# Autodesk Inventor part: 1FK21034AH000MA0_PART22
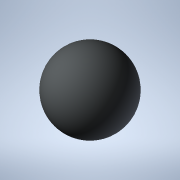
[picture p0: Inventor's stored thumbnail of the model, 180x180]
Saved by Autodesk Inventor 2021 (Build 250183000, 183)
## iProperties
Created: 2025-04
Part Number: 1FK21034AH000MA0_PART22
Material: Generic
Catalog Web Link: www.3dfindit.com
Description: -Servo synchronous motor
Document SubType Name: Modeling
Designer: psAdmin
Mass: 0.113097 g
Surface Area: 1.13097 cm^2
Volume: 0.113097 cm^3
Density: 1 g/cm^3
Appearance: PSOLRGB-212-217-219
Category: PARTsolutions
Title: 1FK21034AH000MA0_PART22
Author: Cadenas PARTsolutions
Comments: Servo synchronous motor
Sending System: PARTsolutions
Preprocessor: ST-DEVELOPER v19.3
PSOL_IDENT_0: {$CADENAS_DATA/23d-libs/siemens_ag/_cat_/ec/b7/1fk21034ah000ma0.prj},216 {VTYP=3D},{NB=1FK21034AH000
PSOL_IDENT_1: MA0_PART22},{LINA=1FK21034AH000MA0_PART22},{NN=1FK21034AH000MA0_PART22},{NOPRJ=TRUE},{DATE=19.08.202
PSOL_IDENT_2: 5 14:01:05},{GEOMDATE=30.07.2025 02:01:02},{VERSION=},{LINEID=10},{WBVAR=},{WBNUMERIC=}  {NB=1FK2103
PSOL_IDENT_3: 4AH000MA0_PART22},{LINA=1FK21034AH000MA0_PART22},{KT=DUMMY},{PREVIEW=../../../_pool_/7c/50/p_d211_xx
PSOL_IDENT_4: _00932j.png},{DESCSHORT=SIMOTICS S-1FK2 HD, SINAMICS S210 3AC 400V-480V, 1.01 Nm, 4500 rpm},{DESCLON
PSOL_IDENT_5: G=SIMOTICS S-1FK2 HD servo motor M0=1.27 Nm; PN = 0.48 kW at nN=4500 rpm (380-480 V); PN = 0.3 kW at
PSOL_IDENT_6: nN=2500 rpm (200-240 V); degree of protection IP64; cylindrical shaft D14 x 30 mm; absolute encoder
PSOL_IDENT_7: 22-bit + 12-bit multiturn (encoder AM22DQC); with OCC interface; plug size M17, rotatable; SIMOTICS
PSOL_IDENT_8: S-1FK2 servomotorfor a wide range of uses in industrial environments. SIMOTICS S‑1FK2 servomotors a
PSOL_IDENT_9: re compact synchronous motors with a high dynamic performance that set themselves apart as a result
PSOL_IDENT_10: of their high power density, degree of protection and overload capability. The motors are available
PSOL_IDENT_11: in two variants: as High Dynamic variant (highest dynamic performance as a result of the low intrins
PSOL_IDENT_12: ic moment of inertia for applications demanding a high dynamic performance with low moved masses) -
PSOL_IDENT_13: and as Compact variant (precise and stable closed-loop control for medium up to large moved masses a
PSOL_IDENT_14: s a result of a medium intrinsic moment of inertia). SIMOTICSS‑1FK2 servomotors fully exploit their
PSOL_IDENT_15: strengths in a system with the SINAMICSS210 frequency converter and simple connection using the one
PSOL_IDENT_16: cable connection (OCC). Advantages include the short control and positioning times, fast and precise
PSOL_IDENT_17: correction of disturbing quantities as well as stable control with a high dynamic performance. The
PSOL_IDENT_18: servo motors can be configured to address a wide range of requirements. For example with and without
PSOL_IDENT_19: holding brake, IP64 or IP65 degree of protection, singleturn or multiturn absolute encoders - to na
PSOL_IDENT_20: me just a few. Further, the servomotors are available in different shaft heights extending from 20 t
PSOL_IDENT_21: o 100. A shaft sealing ring is available to achieve an IP65 degree of protection and for subsequent
PSOL_IDENT_22: mounting at the motor or as spare part. SIMOTICS - the optimum motor for each and every motion contr
PSOL_IDENT_23: ol application.},{INTNO=4034106444822},{SUPPLIERALTNO=1FK2103-4AH00-0MA0},{MANUID=1FK21034AH000MA0},
PSOL_IDENT_24: {MANUNAME=Siemens},{MANUTYPEDESC=SYNCHRONOUS MOTOR 1FK2 HD 1,27 NM},{AAU732=SIMOTICS},{AAO057=S-1FK2
PSOL_IDENT_25: },{AAU734=SIMOTICS S-1FK2 HD servo motor M0=1.27 Nm; PN = 0.48 kW at nN=4500 rpm (380-480 V); PN = 0
PSOL_IDENT_26: .3 kW at nN=2500 rpm (200-240 V); degree of protection IP64; cylindrical shaft D14 x 30 mm; absolute
PSOL_IDENT_27: encoder 22-bit + 12-bit multiturn (encoder AM22DQC); with OCC interface; plug size M17, rotatable;}
PSOL_IDENT_28: ,{AAW338=SYNCHRONOUS MOTOR 1FK2 HD 1,27 NM},{AAO742=SIMOTICS},{AAO663=4034106444822},{NOCUPEROU=1},{
PSOL_IDENT_29: PRICEQUANTITY=1},{QUANTITYMIN=1},{QUANTITYINT=1},{CTN=85015100},{COO=RO},{AAO676=1FK2103-4AH00-0MA0}
PSOL_IDENT_30: ,{AAO677=Siemens AG},{ORDERUNIT=C62},{CONTENTUNIT=C62}
NB: 1FK21034AH000MA0_PART22
NT: Servo synchronous motor
NBSYN: $MANUID._PART22
LINA: 1FK21034AH000MA0_PART22
CATALOG: SIEMENS
PREVIEW: ../../../_pool_/7c/50/p_d211_xx_00932j.png
DESCSHORT: SIMOTICS S-1FK2 HD, SINAMICS S210 3AC 400V-480V, 1.01 Nm, 4500 rpm
DESCLONG: SIMOTICS S-1FK2 HD servo motor M0=1.27 Nm; PN = 0.48 kW at nN=4500 rpm (380-480 V); PN = 0.3 kW at nN=2500 rpm (200-240 V); degree of protection IP64; cylindric
INTNO: 4034106444822
SUPPLIERALTNO: 1FK2103-4AH00-0MA0
MANUID: 1FK21034AH000MA0
MANUNAME: Siemens
MANUTYPEDESC: SYNCHRONOUS MOTOR 1FK2 HD 1,27 NM
AAU732: SIMOTICS
AAO057: S-1FK2
AAU734: SIMOTICS S-1FK2 HD servo motor M0=1.27 Nm; PN = 0.48 kW at nN=4500 rpm (380-480 V); PN = 0.3 kW at nN=2500 rpm (200-240 V); degree of protection IP64; cylindric
AAW338: SYNCHRONOUS MOTOR 1FK2 HD 1,27 NM
AAO742: SIMOTICS
AAO663: 4034106444822.0
NOCUPEROU: 1
PRICEQUANTITY: 1
QUANTITYMIN: 1
QUANTITYINT: 1
CTN: 85015100
COO: RO
ARTICLENO: 1FK21034AH000MA0_PART22
BOMINFO: 1FK21034AH000MA0_PART22
CREATOR: CADENAS GmbH
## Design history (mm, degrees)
feature "2025_04_17_15_01_37_0314"
body "Solid1"
